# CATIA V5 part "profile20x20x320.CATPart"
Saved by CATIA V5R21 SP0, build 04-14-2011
Part number: profile 20x20x320
Bounding box of the stored display mesh (mm): x -24.289 to -4.289, y -1.335 to 18.665, z 0 to 320
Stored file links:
  C:\Users\2027.DESARCY-LEMIE30\Desktop\V15(20.03.2023)\profile20x20x320.CATPart
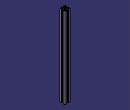
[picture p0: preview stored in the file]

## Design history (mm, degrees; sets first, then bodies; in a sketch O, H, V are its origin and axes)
Body1 (main body)
  Sketch1 on xy-plane, origin (0, 0, 0), H (1, 0, 0), V (0, 1, 0)
    point P1 (-17.2892, 11.6647)
    line L1 (-16.2892, 11.6647) -> (-12.2892, 11.6647)
    point P2 (-11.2892, 11.6647)
    line L2 (-11.2892, 10.6647) -> (-11.2892, 6.6647)
    point P3 (-11.2892, 5.6647)
    line L3 (-12.2892, 5.6647) -> (-16.2892, 5.6647)
    point P4 (-17.2892, 5.6647)
    line L4 (-17.2892, 6.6647) -> (-17.2892, 10.6647)
    point P5 (-24.2892, 18.6647)
    point P6 (-4.2892, 18.6647)
    point P7 (-4.2892, -1.3353)
    line L5 (-11.1892, 18.6647) -> (-11.1892, 16.6647)
    point P8 (-11.1892, 18.6647)
    point P10 (-11.1892, 18.6647)
    point P11 (-17.3892, 18.6647)
    line L6 (-17.3892, 18.6647) -> (-17.3892, 16.6647)
    point P12 (-17.3892, 18.6647)
    line L7 (-11.1892, 18.6647) -> (-4.2892, 18.6647)
    point P14 (-11.1892, 18.6647)
    point P15 (-4.2892, 18.6647)
    point P16 (-11.1892, -1.3353)
    point P17 (-17.3892, -1.3353)
    line L8 (-17.3892, -1.3353) -> (-17.3892, 0.6647)
    point P18 (-17.3892, -1.3353)
    line L9 (-11.1892, -1.3353) -> (-11.1892, 0.6647)
    point P20 (-11.1892, -1.3353)
    line L10 (-24.2892, -1.3353) -> (-17.3892, -1.3353)
    point P22 (-24.2892, -1.3353)
    point P23 (-17.3892, -1.3353)
    line L11 (-11.1892, -1.3353) -> (-4.2892, -1.3353)
    point P24 (-11.1892, -1.3353)
    point P25 (-4.2892, -1.3353)
    line L12 (-24.2892, 18.6647) -> (-17.3892, 18.6647)
    point P26 (-24.2892, 18.6647)
    point P27 (-17.3892, 18.6647)
    point P28 (-4.2892, 5.5647)
    point P29 (-4.2892, 11.7647)
    line L13 (-6.2892, 11.7647) -> (-4.2892, 11.7647)
    point P31 (-4.2892, 11.7647)
    line L14 (-4.2892, 5.5647) -> (-6.2892, 5.5647)
    point P32 (-4.2892, 5.5647)
    point P34 (-24.2892, 5.5647)
    point P35 (-24.2892, 11.7647)
    line L15 (-24.2892, 11.7647) -> (-22.2892, 11.7647)
    point P36 (-24.2892, 11.7647)
    line L16 (-24.2892, 5.5647) -> (-22.2892, 5.5647)
    point P38 (-24.2892, 5.5647)
    line L17 (-4.2892, 18.6647) -> (-4.2892, 11.7647)
    point P40 (-4.2892, 18.6647)
    point P41 (-4.2892, 11.7647)
    line L18 (-24.2892, 18.6647) -> (-24.2892, 11.7647)
    point P42 (-24.2892, 18.6647)
    point P43 (-24.2892, 11.7647)
    line L19 (-24.2892, -1.3353) -> (-24.2892, 5.5647)
    point P44 (-24.2892, -1.3353)
    point P45 (-24.2892, 5.5647)
    line L20 (-4.2892, -1.3353) -> (-4.2892, 5.5647)
    point P46 (-4.2892, -1.3353)
    point P47 (-4.2892, 5.5647)
    line L21 (-22.2892, 5.5647) -> (-22.2892, 1.6647)
    line L22 (-21.2892, 0.6647) -> (-17.3892, 0.6647)
    line L23 (-6.2892, 5.5647) -> (-6.2892, 1.6647)
    line L24 (-11.1892, 0.6647) -> (-7.2892, 0.6647)
    line L25 (-11.1892, 16.6647) -> (-7.2892, 16.6647)
    line L26 (-6.2892, 15.6647) -> (-6.2892, 11.7647)
    line L27 (-17.3892, 16.6647) -> (-21.2892, 16.6647)
    line L28 (-22.2892, 15.6647) -> (-22.2892, 11.7647)
    point P48 (-16.2892, 11.6647)
    point P49 (-17.2892, 10.6647)
    point P50 (-17.2892, 6.6647)
    point P52 (-11.2892, 6.6647)
    point P53 (-11.2892, 10.6647)
    point P54 (-12.2892, 11.6647)
    point P55 (-12.2892, 5.6647)
    line L29 (-16.2892, 11.6647) -> (-21.2892, 16.6647)
    line L30 (-17.2892, 10.6647) -> (-22.2892, 15.6647)
    line L31 (-12.2892, 11.6647) -> (-7.2892, 16.6647)
    line L32 (-16.2892, 5.6647) -> (-21.2892, 0.6647)
    line L33 (-17.2892, 6.6647) -> (-22.2892, 1.6647)
    line L34 (-12.2892, 5.6647) -> (-7.2892, 0.6647)
    line L35 (-11.2892, 6.6647) -> (-6.2892, 1.6647)
    line L36 (-11.2892, 10.6647) -> (-6.2892, 15.6647)
    length L5 = 2
    distance P10 P6 = 6.9
    length L6 = 2
    length L8 = 2
    length L9 = 2
    distance P7 P28 = 6.9
    distance P6 P29 = 6.9
    length L13 = 2
    length L14 = 2
    length L15 = 2
    distance P5 P42 = 0
    length L11 = 6.9
    distance P46 P7 = 0
    distance P1 P48 = 1
    distance P49 P1 = 1
    distance P4 P50 = 1
    distance P54 P2 = 1
    distance P2 P3 = 6
    distance P1 P2 = 6
    horizontal: L1 H, L3 H, L7 H, L10 H, L11 H, L12 H, L13 H, L14 H, L15 H, L16 H, L22 H, L24 H, L25 H, L27 H
    vertical: L2 V, L4 V, L5 V, L6 V, L8 V, L9 V, L17 V, L18 V, L19 V, L20 V, L21 V, L23 V, L26 V, L28 V
    coincidence: P10 P8, P11 P12, P6 P15, P8 P14, P16 L5, P17 L6, P17 P18, P16 P20, P23 L8, P24 L9, P20 P24, P27 L6, P5 P26, P29 P31, P28 P32, P34 L14, P35 L13, P34 P38, P35 P36, P40 L7, P41 L13, P6 P40, P42 L7, P43 L13, P44 L11, P45 L14, P38 P45, P46 L11, P47 L14, P49 L4, P50 L4, P52 L2, P53 L2, P55 L3, P22 P44, P25 P46
    fix: P34, P12, P5, P36, P55
  Pad1: profile Sketch1, direction (0, 0, 1), length 320
  Sketch2 on end face of Pad1, origin (0, 0, 320), H (1, 0, 0), V (0, 1, 0)
    circle A1 centre (-14.2892, 8.6647) radius 2.5
    point P1 (-14.2892, 8.6647)
    reference projected line E1 (-12.2892, 11.6647) -> (-16.2892, 11.6647) from edge [face of Pad1 from Sketch1.L1 | end face of Pad1]
    reference projected line E2 (-11.2892, 6.6647) -> (-11.2892, 10.6647) from edge [face of Pad1 from Sketch1.L2 | end face of Pad1]
    radius A1 = 2.5
    distance P1 E1 = 3
    distance P1 E2 = 3
  Pocket1: profile Sketch2, direction (0, 0, -1), length 320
